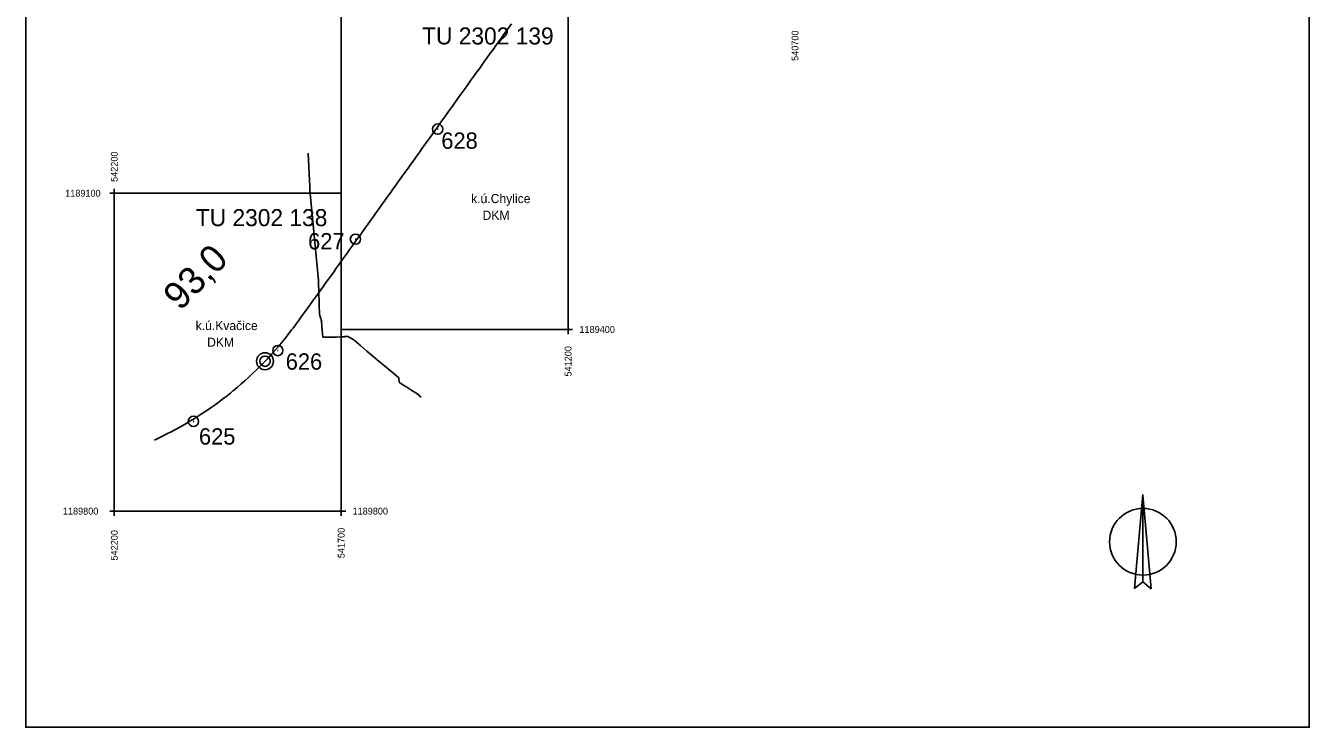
# Model space of a CAD drawing. Extents: x -542395 to -539567, y -1190276 to -1186122.
# Drawn here: x -542395 to -539567, y -1190276 to -1188731 of the extents above; entities that cross this region are included whole.
import ezdxf

# ---------------------------------------------------------------- set-up
doc = ezdxf.new("R2010")
doc.units = 0
for name, color, linetype in [('Vrstva 1', 7, 'Continuous'), ('Vrstva 10', 7, 'Continuous'), ('Vrstva 2', 7, 'Continuous'), ('Vrstva 55', 7, 'Continuous'), ('Vrstva 61', 7, 'Continuous'), ('Vrstva 63', 7, 'Continuous'), ('Vrstva 7', 7, 'Continuous')]:
    doc.layers.add(name, color=color, linetype=linetype)

msp = doc.modelspace()

# ---------------------------------------------------------------- linework, layer by layer
at = {"layer": 'Vrstva 1'}
for points in [[(-541700, -1189400), (-541700, -1188700), (-541200, -1188700), (-541200, -1189400)], [(-542200, -1189800), (-542200, -1189100), (-541700, -1189100), (-541700, -1189800)]]:
    msp.add_lwpolyline(points, close=True, dxfattribs=at)
msp.add_lwpolyline([(-542111.598, -1189643.795), (-542102.758, -1189639.467), (-542093.53, -1189634.885), (-542084.05, -1189630.084), (-542074.437, -1189625.096), (-542065.239, -1189620.204), (-542055.88, -1189615.107), (-542046.977, -1189610.069), (-542040.168, -1189606.119), (-542034.783, -1189602.943), (-542029.733, -1189599.897), (-542025.32, -1189597.184), (-542023.324, -1189595.949), (-542014.094, -1189590.121), (-542004.438, -1189583.855), (-541995.841, -1189578.127), (-541986.508, -1189571.734), (-541977.93, -1189565.663), (-541969.089, -1189559.223), (-541960.759, -1189552.981), (-541951.619, -1189545.93), (-541944.028, -1189539.915), (-541942.256, -1189538.484), (-541938.423, -1189535.37), (-541937.927, -1189534.962), (-541937.928, -1189534.959), (-541937.395, -1189534.519), (-541928.887, -1189527.417), (-541920.21, -1189519.955), (-541912.024, -1189512.709), (-541903.551, -1189505.001), (-541895.263, -1189497.233), (-541887.213, -1189489.502), (-541878.78, -1189481.12), (-541871.391, -1189473.553), (-541867.861, -1189469.863), (-541860.543, -1189462.073), (-541852.696, -1189453.475), (-541845.47, -1189445.324), (-541839.26, -1189438.148), (-541831.83, -1189429.309), (-541824.567, -1189420.421), (-541817.431, -1189411.453), (-541809.22, -1189400.874), (-541806.19, -1189396.904), (-541801.046, -1189390.094), (-541794.292, -1189381.027), (-541787.9, -1189372.342), (-541781.542, -1189363.618), (-541774.998, -1189354.56), (-541769.045, -1189346.279), (-541762.941, -1189337.784), (-541756.627, -1189329), (-541750.132, -1189319.95), (-541745.009, -1189312.816), (-541739.245, -1189304.795), (-541732.905, -1189295.956), (-541727.988, -1189289.1), (-541721.583, -1189280.167), (-541715.848, -1189272.174), (-541710.738, -1189265.055), (-541704.223, -1189255.975), (-541697.763, -1189246.975), (-541691.174, -1189237.784), (-541687.077, -1189232.068), (-541680.916, -1189223.48), (-541674.615, -1189214.695), (-541669.217, -1189207.165), (-541663.828, -1189199.645), (-541658.341, -1189191.999), (-541653.097, -1189184.692), (-541646.491, -1189175.478), (-541640.563, -1189167.212), (-541633.494, -1189157.356), (-541628.845, -1189150.879), (-541622.673, -1189142.266), (-541616.506, -1189133.666), (-541609.876, -1189124.428), (-541603.808, -1189115.965), (-541597.238, -1189106.8), (-541591.672, -1189099.039), (-541586.039, -1189091.167), (-541579.026, -1189081.39), (-541574.877, -1189075.592), (-541572.124, -1189071.75), (-541565.569, -1189062.601), (-541559.311, -1189053.879), (-541552.719, -1189044.673), (-541546.407, -1189035.867), (-541539.505, -1189026.23), (-541533.624, -1189018.027), (-541527.072, -1189008.877), (-541521.344, -1189000.89), (-541515.473, -1188992.7), (-541511.045, -1188986.523), (-541504.904, -1188977.951), (-541498.371, -1188968.853), (-541492.581, -1188960.767), (-541488.033, -1188954.425), (-541482.57, -1188946.796), (-541476.107, -1188937.779), (-541470.355, -1188929.754), (-541463.363, -1188919.992), (-541457.2, -1188911.394), (-541453.227, -1188905.857), (-541446.494, -1188896.482), (-541439.771, -1188887.108), (-541433.488, -1188878.339), (-541426.896, -1188869.148), (-541420.266, -1188859.905), (-541414.151, -1188851.375), (-541407.801, -1188842.523), (-541400.091, -1188831.755), (-541394.763, -1188824.326), (-541388.429, -1188815.492), (-541382.59, -1188807.348), (-541377.39, -1188800.084), (-541376.574, -1188798.947), (-541370.21, -1188790.082), (-541364.743, -1188782.46), (-541359.153, -1188774.654), (-541353.011, -1188766.095), (-541346.868, -1188757.534), (-541340.594, -1188748.776), (-541336.438, -1188742.972), (-541330.873, -1188735.219), (-541324.822, -1188726.775)], dxfattribs=at)
at = {"layer": 'Vrstva 10'}
for p, q in [((-539951.9, -1189970.06), (-539933.81, -1189763.42)), ((-539933.36, -1189955.78), (-539933.36, -1189763.3)), ((-539933.36, -1189955.78), (-539933.36, -1189763.3)), ((-539933.3, -1189764.72), (-539915.18, -1189971.38)), ((-539933.3, -1189764.72), (-539915.18, -1189971.38)), ((-539933.36, -1189955.78), (-539951.9, -1189970.06)), ((-539915.18, -1189971.38), (-539933.36, -1189955.78)), ((-539915.18, -1189971.38), (-539933.36, -1189955.78))]:
    msp.add_line(p, q, dxfattribs=at)
msp.add_circle((-539933.36, -1189867.36), 73.4294, dxfattribs=at)
at = {"layer": 'Vrstva 55'}
for p, q in [((-541772.85, -1189011.87), (-541769.93, -1189071.81)), ((-541769.93, -1189071.81), (-541769.3, -1189084.77)), ((-541769.3, -1189084.77), (-541769.15, -1189087.77)), ((-541768.77, -1189095.46), (-541768.72, -1189096.61)), ((-541768.72, -1189096.61), (-541768.63, -1189098.46)), ((-541768.63, -1189098.46), (-541768.42, -1189100.67)), ((-541768.42, -1189100.67), (-541750.16, -1189292.16)), ((-541750.16, -1189292.16), (-541750.01, -1189296.85)), ((-541748.45, -1189345.11), (-541747.74, -1189367.59)), ((-541747.74, -1189367.59), (-541746.6, -1189370.93)), ((-541746.6, -1189370.93), (-541746.28, -1189371.86)), ((-541746.28, -1189371.86), (-541744.87, -1189376.01)), ((-541744.87, -1189376.01), (-541743.97, -1189378.66)), ((-541740.19, -1189416.59), (-541736.53, -1189416.75)), ((-541736.53, -1189416.75), (-541723.9, -1189417.27)), ((-541723.9, -1189417.27), (-541710.5, -1189416.79)), ((-541693.47, -1189415.89), (-541692.28, -1189415.78)), ((-541692.28, -1189415.78), (-541685.5, -1189415.16)), ((-541685.5, -1189415.16), (-541671.87, -1189423.02)), ((-541671.87, -1189423.02), (-541670.86, -1189423.89)), ((-541604.86, -1189479.79), (-541582.69, -1189498.39)), ((-541561.7, -1189523.21), (-541557.64, -1189525.76)), ((-541544.17, -1189534.21), (-541540.85, -1189536.29))]:
    msp.add_line(p, q, dxfattribs=at)
for points in [[(-541769.15, -1189087.77), (-541768.96, -1189091.75), (-541768.77, -1189095.46)], [(-541750.01, -1189296.85), (-541749.3, -1189318.71), (-541748.56, -1189341.7), (-541748.45, -1189345.11)], [(-541743.97, -1189378.66), (-541743.21, -1189380.88), (-541742.74, -1189393.78)], [(-541742.74, -1189393.78), (-541741.93, -1189401.04), (-541740.94, -1189409.93), (-541740.19, -1189416.59)], [(-541710.5, -1189416.79), (-541698.45, -1189416.35), (-541693.47, -1189415.89)], [(-541670.86, -1189423.89), (-541657.1, -1189435.7), (-541643.5, -1189447.45), (-541612.07, -1189474.13), (-541604.86, -1189479.79)], [(-541582.69, -1189498.39), (-541573.32, -1189506.42), (-541572.81, -1189509.22)], [(-541572.81, -1189509.22), (-541571.34, -1189517.16), (-541569.67, -1189518.21), (-541561.7, -1189523.21)], [(-541557.64, -1189525.76), (-541553.06, -1189528.63), (-541544.17, -1189534.21)], [(-541540.85, -1189536.29), (-541533.69, -1189540.79), (-541523.85, -1189548.88)]]:
    msp.add_lwpolyline(points, dxfattribs=at)
at = {"layer": 'Vrstva 61'}
for p, q in [((-542200, -1189090), (-542200, -1189110)), ((-542210, -1189100), (-542190, -1189100)), ((-541210, -1189400), (-541190, -1189400)), ((-541200, -1189390), (-541200, -1189410)), ((-542210, -1189800), (-542190, -1189800)), ((-542200, -1189790), (-542200, -1189810)), ((-541710, -1189800), (-541690, -1189800)), ((-541700, -1189790), (-541700, -1189810))]:
    msp.add_line(p, q, dxfattribs=at)
at = {"layer": 'Vrstva 63'}
for p, q in [((-541488.134, -1188958.687), (-541486.634, -1188958.687)), ((-541669.368, -1189201.14), (-541667.868, -1189201.14)), ((-541840.355, -1189446.416), (-541838.855, -1189446.416)), ((-542026.441, -1189602.25), (-542024.941, -1189602.25))]:
    msp.add_line(p, q, dxfattribs=at)
msp.add_lwpolyline([(-542395.2545, -1186122.471), (-539566.7735, -1186122.471), (-539566.7735, -1190275.905), (-542395.2545, -1190275.905)], close=True, dxfattribs=at)
for centre in [(-541487.384, -1188958.687), (-541668.618, -1189201.14), (-541839.605, -1189446.416), (-542025.691, -1189602.25)]:
    msp.add_circle(centre, 11.3402, dxfattribs=at)
at = {"layer": 'Vrstva 7'}
for radius in [18.685, 11.2779]:
    msp.add_circle((-541867.861, -1189469.863), radius, dxfattribs=at)

# ---------------------------------------------------------------- texts
at = {"layer": 'Vrstva 1'}
for s, p in [('k.ú.Chylice', (-541413.703, -1189121.735)), ('DKM', (-541388.5012, -1189158.573)), ('k.ú.Kvačice', (-542020.718, -1189401.321)), ('DKM', (-541995.5162, -1189438.159))]:
    msp.add_text(s, height=20, dxfattribs=at).set_placement(p)
at = {"layer": 'Vrstva 2'}
for s, p in [('TU 2302 139', (-541521.7681, -1188772.5)), ('TU 2302 138', (-542020.3891, -1189172.5))]:
    msp.add_text(s, height=37.500003, dxfattribs=at).set_placement(p)
at = {"layer": 'Vrstva 61'}
for s, p in [('540700', (-540692.5, -1188808.6133)), ('542200', (-542192.5, -1189075)), ('541200', (-541192.5, -1189503.5358)), ('542200', (-542192.5, -1189908.6133)), ('541700', (-541692.5, -1189903.5358))]:
    msp.add_text(s, height=15, rotation=90, dxfattribs=at).set_placement(p)
for s, p in [('1189100', (-542308.1427, -1189107.5)), ('1189400', (-541175, -1189407.5)), ('1189800', (-542313.2202, -1189807.5)), ('1189800', (-541675, -1189807.5))]:
    msp.add_text(s, height=15, dxfattribs=at).set_placement(p)
at = {"layer": 'Vrstva 63'}
for s, p in [('628', (-541479.41, -1189002.206)), ('627', (-541772.958, -1189223.683)), ('626', (-541822.249, -1189488.524)), ('625', (-542013.443, -1189653.467))]:
    msp.add_text(s, height=36, dxfattribs=at).set_placement(p)
at = {"layer": 'Vrstva 7'}
msp.add_text('93,0', height=60, rotation=45.6816251, dxfattribs=at).set_placement((-542054.652, -1189360.68))

doc.saveas('drawing.dxf')
